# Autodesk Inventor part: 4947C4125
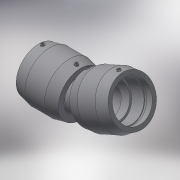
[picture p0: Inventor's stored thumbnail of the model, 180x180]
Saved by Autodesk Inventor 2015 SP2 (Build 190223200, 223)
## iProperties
Created: 2017-06
Part Number: 4947C4125
Material: Generic
Description: PLASSON ADJUSTABLE ELBOW 125
Document SubType Name: Modeling
Designer: KIM
Mass: 2477.74 g
Surface Area: 3615.49 cm^2
Volume: 2477.74 cm^3
Density: 1 g/cm^3
Appearance: Default
Author: KIM
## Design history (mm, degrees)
derived "4947C4.ipt"
feature "Solid1::4947C4.ipt"
tag "TaggingFeature1"
body "Solid1"
other parameters: "d0" = 152.8, "d2" = 157, "d3" = 85, "d4" = 42.5, "d5" = 141.3, "d7" = 125, "d8" = 168 deg, "d10" = 34, "d11" = 11.33333, "d29" = 95, "d30" = 15, "d31" = 61.12, "d34" = 5 deg, "d41" = 4, "d42" = 14, "d43" = 0, "d48" = 112.5, "d49" = 24 deg, "d50" = 382, "d51" = 78 deg, "d52" = 90 deg, "d55" = 33.9, "d57" = 168 deg, "d58" = 6.78, "d60" = 43.02259, "d62" = 3, "d63" = 0, "d_" = 125, "L_" = 382, "L_1" = 85, "D_" = 157, "A_" = 95, "d_2" = 12, "L_0" = 148, "d54" = 67.8, "d59" = 143.40864
